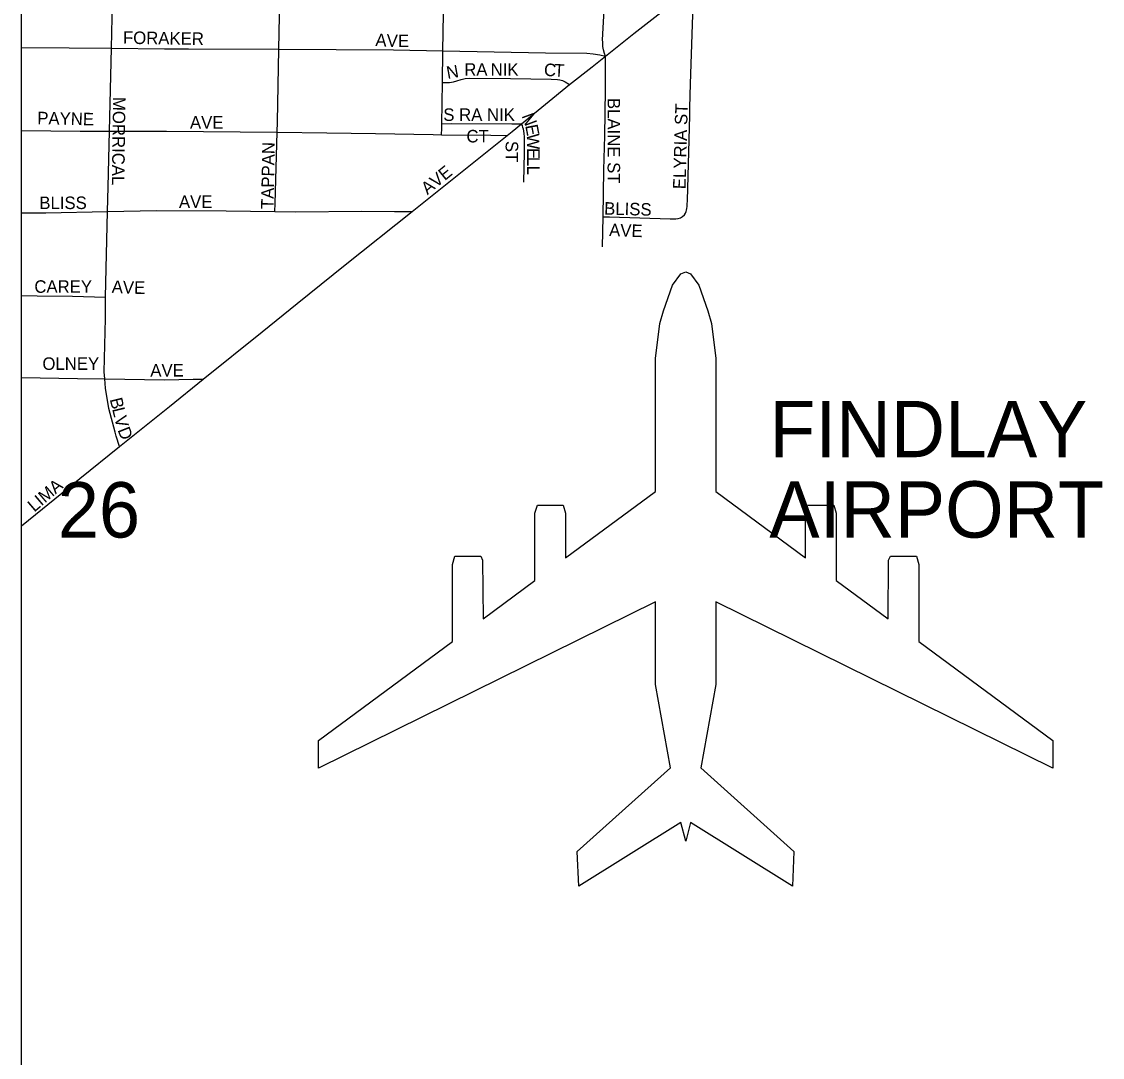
# Model space of a CAD drawing. Extents: x 0 to 68, y 0 to 52.9.
# Drawn here: x 49.517 to 51.676, y 47.729 to 49.797 of the extents above; entities that cross this region are included whole.
import ezdxf

# ---------------------------------------------------------------- set-up
doc = ezdxf.new("R2010")
doc.units = 0
doc.layers.add('Default', color=7, linetype='Continuous')

msp = doc.modelspace()

# ---------------------------------------------------------------- linework, layer by layer
at = {"layer": 'Default'}
msp.add_line((49.5172, 34.4614), (49.5172, 52.9414), dxfattribs=at)
for points in [[(49.6966, 49.7435), (49.6989, 49.8358), (49.6997, 49.9097)], [(50.0309, 49.7415), (50.0342, 49.907)], [(50.3586, 49.7383), (50.3598, 49.8123), (50.3633, 49.9053)], [(50.6835, 49.7277), (50.6817, 49.7328), (50.6796, 49.7406), (50.6791, 49.7435), (50.6784, 49.7473), (50.6782, 49.751), (50.6779, 49.7559), (50.6777, 49.7606), (50.6802, 49.8076), (50.6845, 49.9029)], [(50.6835, 49.7277), (50.7399, 49.7728), (50.8302, 49.8438), (50.8601, 49.8674)], [(50.8375, 49.4077), (50.8411, 49.4108), (50.8431, 49.4143), (50.8446, 49.4173), (50.8454, 49.4202), (50.846, 49.4237), (50.8465, 49.4273), (50.8467, 49.4314), (50.8471, 49.4398), (50.8519, 49.6091), (50.852, 49.6256), (50.8534, 49.6728), (50.8595, 49.8512), (50.8601, 49.8674)], [(49.5172, 49.745), (49.6123, 49.7446), (49.6966, 49.7435)], [(49.6925, 49.578), (49.6966, 49.7435)], [(49.6966, 49.7435), (49.8024, 49.7421), (49.8505, 49.7427), (50.0309, 49.7415)], [(50.0276, 49.5762), (50.0281, 49.5966), (50.0309, 49.7415)], [(50.0309, 49.7415), (50.2601, 49.7401), (50.3586, 49.7383)], [(50.3581, 49.6753), (50.3586, 49.7383)], [(50.3586, 49.7383), (50.5637, 49.7347), (50.6463, 49.7335), (50.6589, 49.7325), (50.6722, 49.7302), (50.6835, 49.7277)], [(50.6116, 49.6715), (50.6565, 49.7062), (50.6835, 49.7277)], [(50.6787, 49.4073), (50.6803, 49.5008), (50.682, 49.569), (50.6832, 49.6605), (50.6835, 49.7277)], [(50.3563, 49.5929), (50.3581, 49.6753)], [(50.3581, 49.6753), (50.3717, 49.6754), (50.3798, 49.6765), (50.3866, 49.6787), (50.3952, 49.6815), (50.4033, 49.6833), (50.4117, 49.6837), (50.4934, 49.6835), (50.575, 49.6819), (50.5875, 49.6813), (50.5922, 49.6808), (50.5977, 49.6792), (50.6027, 49.6764), (50.6116, 49.6715)], [(50.5157, 49.5927), (50.6116, 49.6715)], [(50.3561, 49.571), (50.3563, 49.5838), (50.3563, 49.5929)], [(50.3563, 49.5929), (50.3749, 49.593), (50.4965, 49.5927), (50.5157, 49.5927)], [(50.487, 49.5697), (50.4969, 49.5776), (50.5157, 49.5927)], [(50.5202, 49.4764), (50.5218, 49.5356), (50.522, 49.5421), (50.5219, 49.5519), (50.5219, 49.5585), (50.5218, 49.5636), (50.5216, 49.5676), (50.521, 49.573), (50.5202, 49.5787), (50.5194, 49.5823), (50.5186, 49.5855), (50.5174, 49.5894), (50.5157, 49.5927)], [(49.5172, 49.5792), (49.6343, 49.5781), (49.6925, 49.578)], [(49.6888, 49.4179), (49.6898, 49.4668), (49.6925, 49.578)], [(49.6925, 49.578), (49.8065, 49.5778), (50.0276, 49.5762)], [(50.0231, 49.4178), (50.0235, 49.4334), (50.0276, 49.5762)], [(50.0276, 49.5762), (50.1269, 49.575), (50.2238, 49.5734), (50.3392, 49.5711), (50.3561, 49.571)], [(50.297, 49.4177), (50.487, 49.5697)], [(50.3561, 49.571), (50.4546, 49.57), (50.487, 49.5697)], [(49.5172, 49.4149), (49.5657, 49.4153), (49.6888, 49.4179)], [(49.685, 49.2466), (49.6888, 49.4179)], [(49.6888, 49.4179), (49.7868, 49.4199), (49.926, 49.4192), (50.0231, 49.4178)], [(49.88, 49.0831), (49.9974, 49.1777), (50.0678, 49.234), (50.1638, 49.3111), (50.297, 49.4177)], [(50.0231, 49.4178), (50.0651, 49.4172), (50.1962, 49.4183), (50.2617, 49.4179), (50.297, 49.4177)], [(50.6777, 49.3473), (50.6787, 49.4073)], [(50.6787, 49.4073), (50.6914, 49.407), (50.8129, 49.4027), (50.8194, 49.4027), (50.8242, 49.4031), (50.8283, 49.4039), (50.8331, 49.4052), (50.8375, 49.4077)], [(50.8436, 48.1604), (50.8342, 48.1974), (50.6301, 48.0709), (50.6272, 48.1397), (50.8135, 48.3068), (50.7834, 48.4731), (50.7834, 48.6381), (50.1103, 48.3064), (50.1103, 48.3611), (50.378, 48.5591), (50.378, 48.713), (50.3827, 48.7293), (50.4345, 48.7293), (50.4381, 48.7212), (50.4392, 48.6044), (50.5426, 48.6809), (50.5426, 48.8152), (50.5474, 48.8315), (50.5992, 48.8315), (50.6039, 48.8152), (50.6039, 48.7262), (50.7834, 48.8589), (50.7834, 49.1241), (50.7922, 49.1943), (50.7995, 49.2193), (50.8175, 49.2704), (50.8341, 49.2931), (50.8436, 49.297)], [(50.8436, 49.297), (50.853, 49.2931), (50.8696, 49.2704), (50.8876, 49.2193), (50.8949, 49.1943), (50.9037, 49.1241), (50.9037, 48.8589), (51.0832, 48.7262), (51.0832, 48.8152), (51.0879, 48.8315), (51.1397, 48.8315), (51.1445, 48.8152), (51.1445, 48.6809), (51.2479, 48.6044), (51.249, 48.7212), (51.2526, 48.7293), (51.3044, 48.7293), (51.3091, 48.713), (51.3091, 48.5591), (51.5768, 48.3611), (51.5768, 48.3064), (50.9037, 48.6381), (50.9037, 48.4731), (50.8736, 48.3068), (51.0599, 48.1397), (51.057, 48.0709), (50.853, 48.1974), (50.8436, 48.1604)], [(49.5172, 49.2498), (49.5483, 49.2495), (49.619, 49.2483), (49.685, 49.2466)], [(49.6832, 49.0833), (49.682, 49.0977), (49.6845, 49.2043), (49.685, 49.2466)], [(49.5172, 49.0862), (49.6291, 49.0841), (49.6832, 49.0833)], [(49.7127, 48.9481), (49.7063, 48.9691), (49.704, 48.977), (49.6915, 49.0246), (49.6846, 49.065), (49.6832, 49.0833)], [(49.6832, 49.0833), (49.8028, 49.0814), (49.8596, 49.0827), (49.88, 49.0831)], [(49.7127, 48.9481), (49.8123, 49.0283), (49.88, 49.0831)], [(49.6113, 48.8663), (49.6334, 48.8843), (49.7127, 48.9481)], [(49.5172, 48.7897), (49.6113, 48.8663)]]:
    msp.add_lwpolyline(points, dxfattribs=at)

# ---------------------------------------------------------------- texts
for s, height, rotation, p in [('FORAKER', 0.025, 359.1175, (49.7195, 49.7525)), ('A', 0.025, 356.6977, (50.2234, 49.7481)), ('V', 0.025, 357.8085, (50.2459, 49.7468)), ('E', 0.025, 359.8324, (50.2688, 49.7459)), ('N', 0.025, 10.1709, (50.3681, 49.6821)), ('RA', 0.025, 0, (50.4013, 49.6887)), ('NIK', 0.025, 0, (50.4541, 49.6887)), ('C', 0.025, 356.3297, (50.56, 49.6887)), ('T', 0.025, 357.2145, (50.5802, 49.6874)), ('MORRICAL', 0.025, 269.2156, (49.6998, 49.6465)), ('BLAINE ST', 0.025, 270, (50.6876, 49.6444)), ('ELYRIA ST', 0.025, 88.3873, (50.8432, 49.4619)), ('PAYNE', 0.025, 358.7554, (49.5483, 49.5919)), ('AVE', 0.025, 0, (49.8535, 49.5831)), ('S RA NIK', 0.025, 0, (50.3595, 49.5985)), ('N', 0.025, 290.1979, (50.5157, 49.6087)), ('E', 0.025, 280.6348, (50.523, 49.5891)), ('CT', 0.025, 0, (50.4057, 49.5555)), ('W', 0.025, 271.749, (50.5261, 49.5728)), ('TAPPAN', 0.025, 88.9396, (50.0204, 49.4223)), ('ST', 0.025, 270, (50.484, 49.5586)), ('E', 0.025, 270, (50.527, 49.5444)), ('L', 0.025, 269.9942, (50.527, 49.5268)), ('AVE', 0.025, 39.2926, (50.3279, 49.45)), ('L', 0.025, 269.9942, (50.527, 49.5092)), ('BLISS', 0.025, 0, (49.5526, 49.4225)), ('AVE', 0.025, 0, (49.8315, 49.4247)), ('BLISS', 0.025, 358.5266, (50.6805, 49.4115)), ('AVE', 0.025, 358.0845, (50.6904, 49.3685)), ('CAREY', 0.025, 0, (49.5427, 49.2553)), ('A', 0.025, 357.4639, (49.6969, 49.2553)), ('V', 0.025, 357.4421, (49.7189, 49.2543)), ('E', 0.025, 359.3429, (49.7418, 49.2533)), ('OLNEY', 0.025, 0, (49.5588, 49.1014)), ('AVE', 0.025, 0, (49.7743, 49.0881)), ('B', 0.025, 283.6828, (49.6931, 49.0427)), ('L', 0.025, 283.6785, (49.6978, 49.0234)), ('FINDLAY', 0.1125, 0, (51.0107, 48.9271)), ('V', 0.025, 284.2738, (49.702, 49.0061)), ('D', 0.025, 291.5354, (49.7085, 48.9815)), ('LIMA', 0.025, 40.4282, (49.5425, 48.8164)), ('26', 0.1105, 0, (49.5895, 48.7667)), ('AIRPORT', 0.1125, 0, (51.0107, 48.7665))]:
    msp.add_text(s, height=height, rotation=rotation, dxfattribs=at).set_placement(p)

doc.saveas('drawing.dxf')
